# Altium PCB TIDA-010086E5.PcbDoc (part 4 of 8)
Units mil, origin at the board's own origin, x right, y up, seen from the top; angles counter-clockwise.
Board outline 6400 x 6200 mil, 6 copper layers (Top Layer, Power, AGND, Signal, PGND, Bottom Layer), stack 70.536 mil thick; 717 components, 376 nets, 2259 pads, 2183 vias.
Unrouted connection lines stored in the file: 1424.
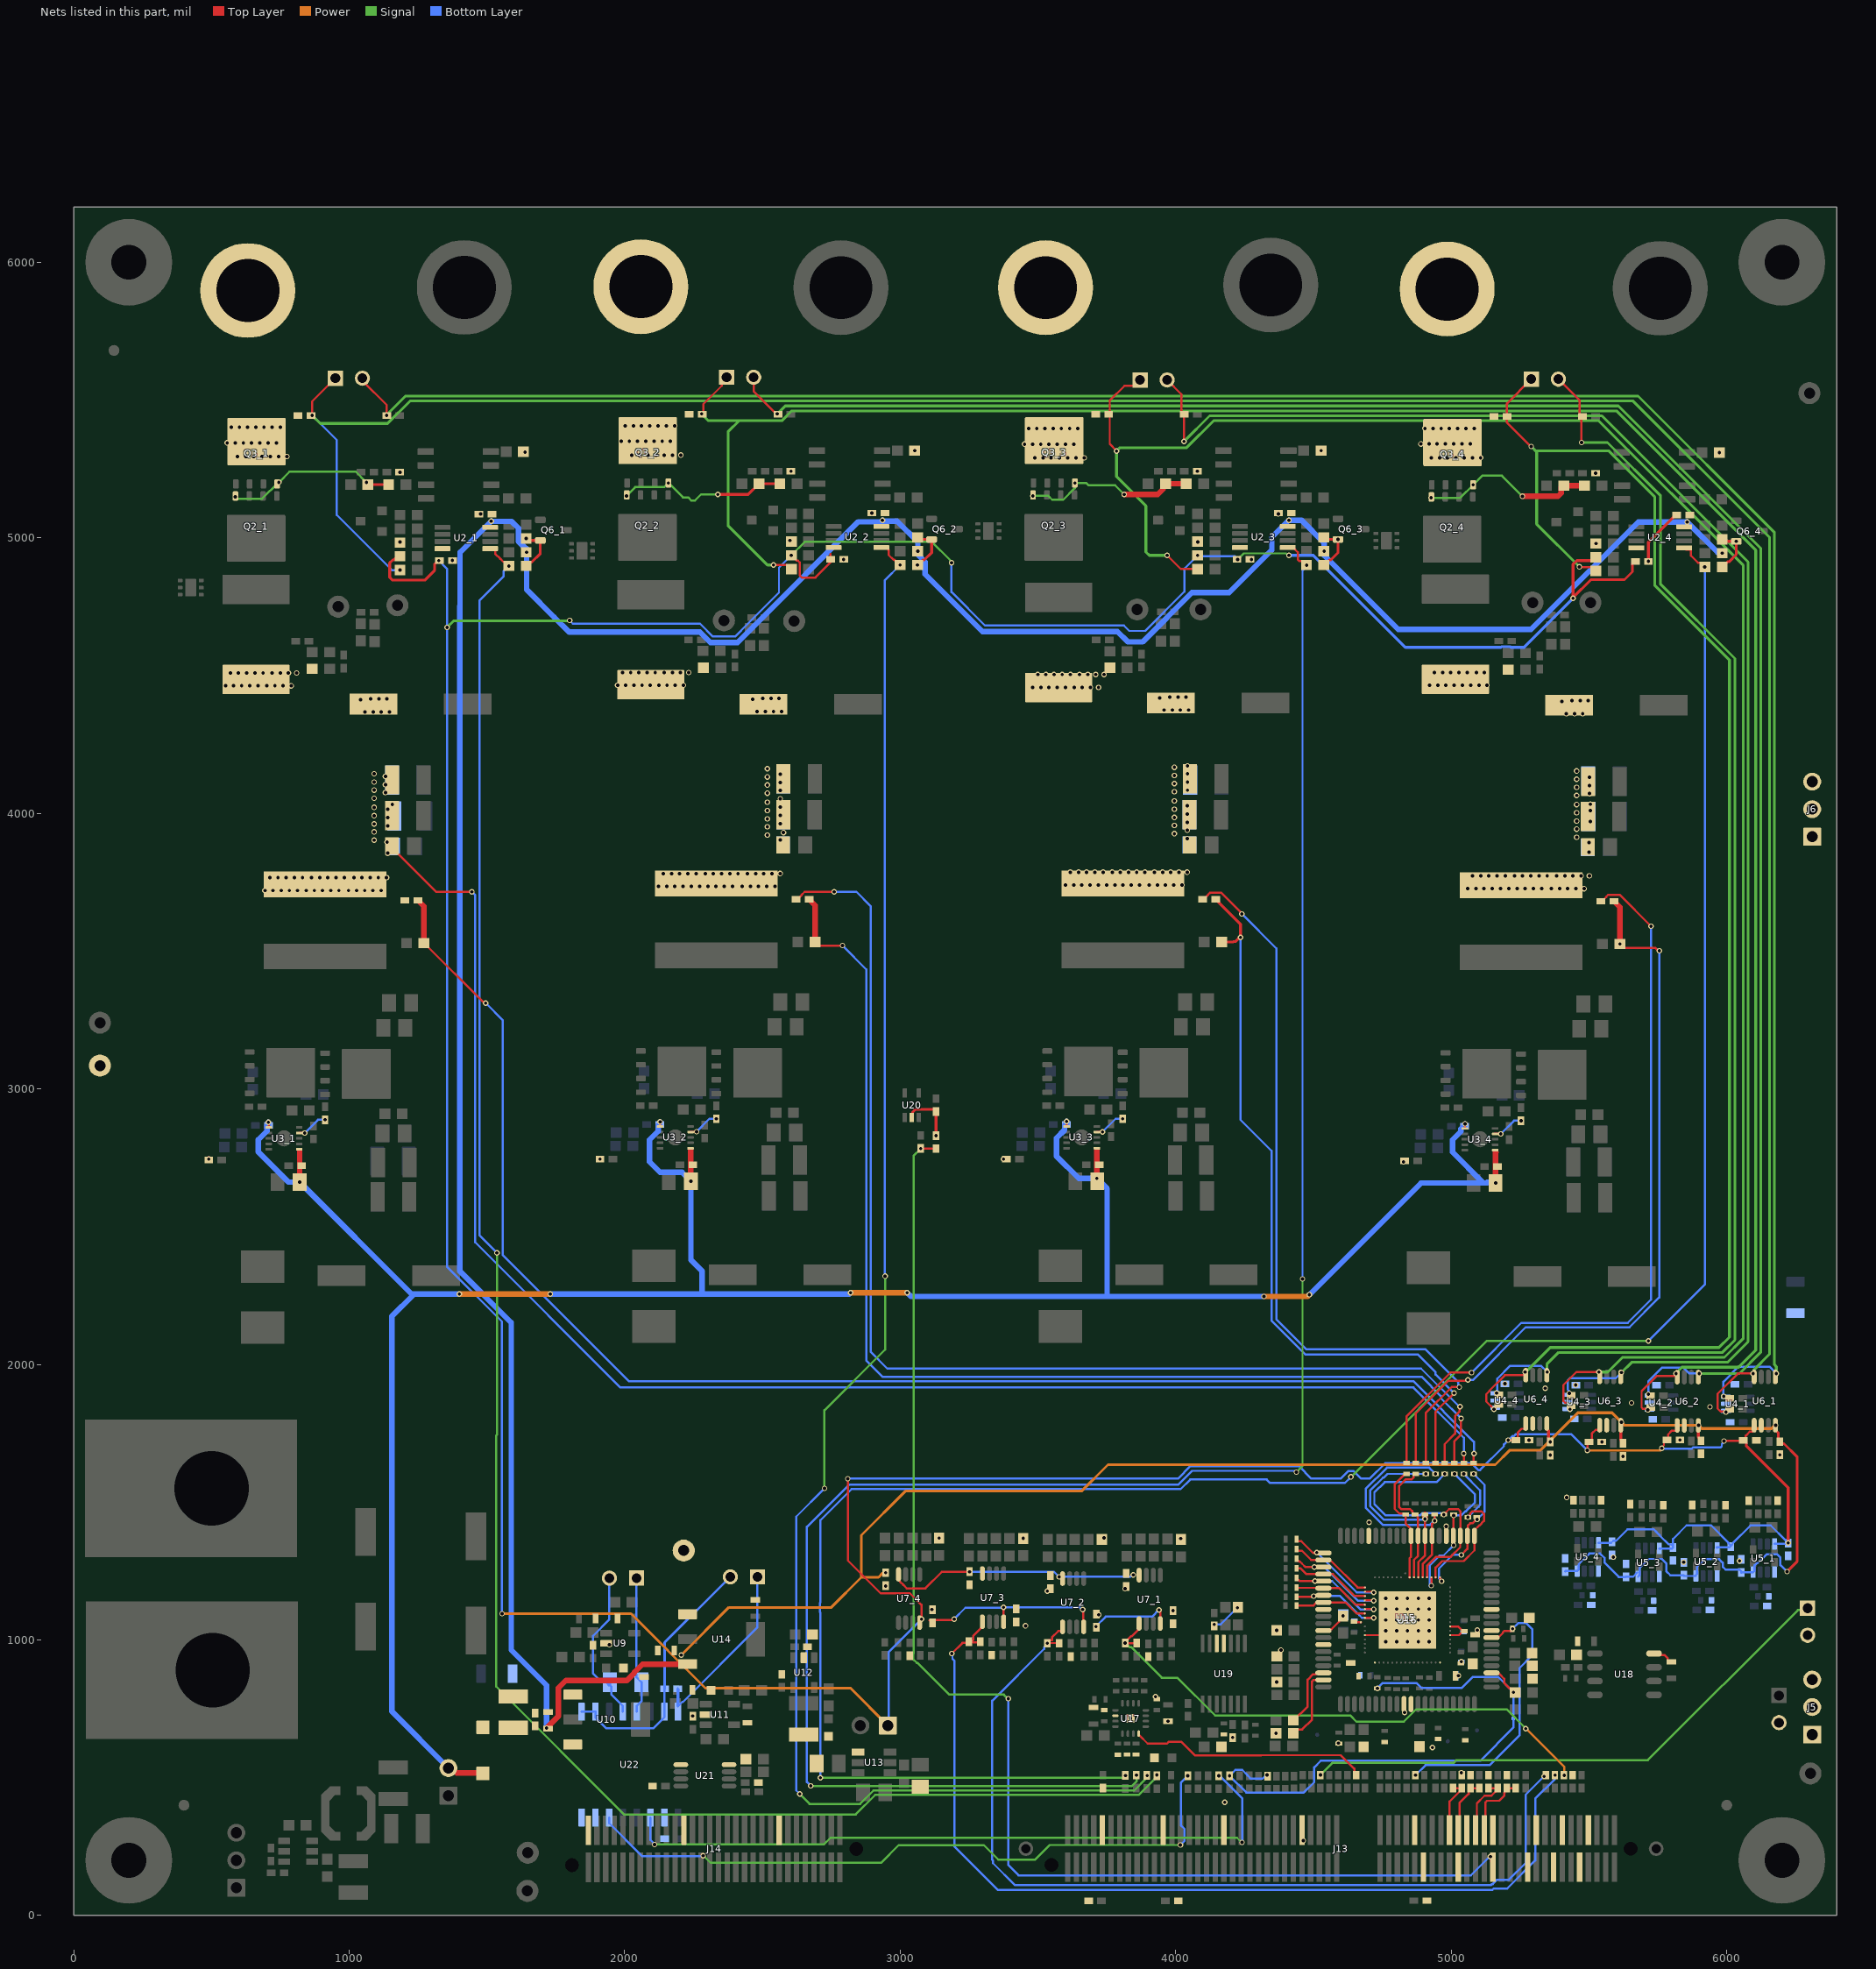
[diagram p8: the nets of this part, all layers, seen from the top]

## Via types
v1: diameter 20, hole 12.5, Top Layer to Bottom Layer, 1408 vias
v2: diameter 20, hole 12, Top Layer to Bottom Layer, tented both sides, 775 vias

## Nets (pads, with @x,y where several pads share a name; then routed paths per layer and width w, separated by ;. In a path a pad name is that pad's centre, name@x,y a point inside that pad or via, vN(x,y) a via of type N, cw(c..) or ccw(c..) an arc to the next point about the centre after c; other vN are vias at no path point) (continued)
10V: C21_1.1 C21_2.1 C21_3.1 C21_4.1 C22_1.2 C22_2.2 C22_3.2 C22_4.2 C26_1.2 C26_2.2 C26_3.2 C26_4.2 J10.2 L3.1 U3_1.1 U3_1.6 U3_2.1 U3_2.6 U3_3.1 U3_3.6 U3_4.1 U3_4.6 | length 9301.3
  Top Layer w7.87: v2(706.18,2878.81) 707.24,2877.75 707.24,2860.39 708.03,2859.61 U3_1.6@708.31,2859.61 ; U3_2.6@2128.43,2863.19 v2(2128.43,2879.92) ; U3_3.6@3603.43,2863.19 v2(3603.43,2881.41) ; U3_4.6@5049.2,2856.35 5049.74,2856.88 5049.74,2872.38 v2(5050.27,2872.91)
  Top Layer w20: v2(820,2661.42) 820,2772.99 ; J10.2@1360,535 1372.17,535 1390.15,517.02 1483.23,517.02 L3.1@1484.97,515.27 ; 2239.39,2775.85 2239.39,2665.73 v2(2240.12,2665) ; v2(3713.66,2675) 3713.66,2776.57 ; v2(5160.9,2658.16) 5160.9,2768.57 5162.07,2769.74
  Power w20: v2(1400,2255) v2(1730,2255) ; v2(2820,2260) v2(3025,2260) ; v2(4320,2246.66) 4478.45,2246.66 4484.46,2252.67 v2(4485,2252.67)
  Bottom Layer w20: v2(706.18,2878.81) 706.18,2868.54 C26_1.2@707.24,2867.48 703.31,2867.48 701.5,2865.67 701.5,2847.01 670,2815.51 670,2771.28 779.86,2661.42 v2(820,2661.42) 1226.42,2255 v2(1400,2255) ; 1230.57,2250.85 1154.52,2174.8 1154.52,740.48 J10.2@1360,535 ; v2(1730,2255) 2280.58,2255 ; v2(2128.43,2879.92) 2127.36,2878.86 C26_2.2@2127.36,2871.06 2123.43,2871.06 2121.61,2869.25 2121.61,2846.2 2090,2814.58 2090,2735.31 2128.26,2697.05 2208.07,2697.05 v2(2240.12,2665) 2240.12,2379.05 2280.58,2338.6 2280.58,2255 ; v2(2820,2260) 2815,2255 2280.58,2255 ; v2(3025,2260) 3038.34,2246.66 3750.8,2246.66 ; v2(3603.43,2881.41) 3603.43,2872.13 C26_3.2@3602.36,2871.06 3598.43,2871.06 3596.61,2869.25 3596.61,2850.77 3567.57,2821.72 3567.57,2755.22 3647.8,2675 v2(3713.66,2675) 3750.8,2637.86 3750.8,2246.66 ; v2(4320,2246.66) 3750.8,2246.66 ; v2(4485,2252.67) 4890.5,2658.16 5116.84,2658.16 ; v2(5050.27,2872.91) 5048.14,2870.79 C26_4.2@5048.14,2864.22 5044.2,2864.22 5034.52,2854.54 5034.52,2845.01 5004.89,2815.38 5004.89,2770.11 5116.84,2658.16 ; 5130.39,2658.16 5116.84,2658.16 ; 5130.39,2661.03 5158.03,2661.03 v2(5160.9,2658.16)
10VA: C23_1.1 C23_2.1 C23_3.1 C23_4.1 C29_1.1 C29_2.1 C29_3.1 C29_4.1 C34_1.1 C34_2.1 C34_3.1 C34_4.1 C39_1.2 C39_2.2 C39_3.2 C39_4.2 C45.2 C48.1 C52.1 C60.1 L3.2 R28_1.2 R28_2.2 R28_3.2 R28_4.2 U2_1.8 U2_2.8 U2_3.8 U2_4.8 U5_1.8 U5_2.8 U5_3.8 U5_4.8 U6_1.8 U6_2.8 U6_3.8 U6_4.8 U7_1.8 U7_2.8 U7_3.8 U7_4.8 U10.3 U14.3 | length 18411.4
  Top Layer w7.87: U7_4.8@2993.8,1237.91 2993.8,1217.53 2998.73,1212.61 2998.73,1211.63 3010.83,1199.53 3023.27,1187.09 3090.97,1187.09 3151.08,1247.2 C39_3.2@3251.51,1247.2 ; v2(3251.33,1247.2) C39_3.2@3257.43,1241.1
  Top Layer w10: U6_4.8@5347.07,1785.42 5347.07,1765.61 5353.14,1759.54 C34_4.1@5353.14,1718.45 ; U6_3.8@5615.12,1779.11 5615.12,1726.05 5623.54,1717.63 C34_3.1@5623.54,1713.7 ; U6_2.8@5896.67,1778.58 5896.67,1735.68 5905.98,1726.37 C34_2.1@5905.98,1722.43 ; v2(6177.37,1779.2) 6177.37,1761.06 6186.67,1751.76 6186.67,1725.38 6199.67,1712.38 6207.78,1712.38 6255,1665.16 6255,1283.95 v2(6218.56,1247.51)
  Top Layer w20: v2(1716.19,680.07) 1759.09,722.97 1759.09,825.61 1786.59,853.1 2007.82,853.1 2035.32,880.6 2035.32,882.96 2064.24,911.89 U14.3@2228.49,911.89
  Power w10: v2(2205,945) 2377.99,1117.99 2749.62,1117.99 2858.67,1227.05 ; v2(2947.19,1244.01) 2945.28,1242.1 2936.07,1242.1 2921.01,1227.05 2858.67,1227.05 ; v2(6177.37,1779.2) 6174.66,1779.2 6162.73,1767.26 5909.13,1767.26 v2(5897.81,1778.58) 5629.17,1778.58 5583.43,1824.32 5459.01,1824.32 5322.58,1687.9 5211.44,1687.9 5159.54,1636 3753.95,1636 3657.95,1540 3019,1540 2858.67,1379.67 2858.67,1227.05
  Bottom Layer w7.87: v2(3251.33,1247.2) 3558.4,1247.2 v2(3576.75,1228.85) 3835.61,1228.85 3842.6,1235.84 v2(3845.85,1235.84) ; C29_4.1@5413.78,1248.4 5415.04,1249.66 U5_4.8@5457.01,1249.66 5461.93,1254.58 5461.93,1274.08 5501.16,1313.31 5540.3,1313.31 5555.78,1297.83 5555.78,1280.68 5608.06,1228.41 C29_3.1@5634.87,1228.41 ; C29_3.1@5634.87,1229.67 5660,1229.67 U5_3.8@5674.95,1244.62 ; U5_3.8@5678.1,1229.67 5683.02,1234.59 5683.02,1260.04 5716.92,1293.95 5764.06,1293.95 5781.25,1276.75 5781.25,1248.24 5794.96,1234.53 C29_2.1@5843.78,1234.53 5843.78,1231.95 U5_2.8@5888.02,1231.95 ; U5_2.8@5886.59,1234.47 5891.68,1239.55 5891.68,1264.43 5920.19,1292.95 5972.4,1292.95 5985.17,1280.17 5985.17,1265.4 5995.32,1255.25 6046,1255.25 6052.82,1248.44 C29_1.1@6052.82,1245.76 ; C29_1.1@6052.82,1244.5 C29_1.1@6052.82,1245.76 ; v2(6218.56,1247.51) 6194.63,1271.44 6194.63,1298.56 6181.85,1311.33 6145.44,1311.33 6132.66,1298.56 6131.9,1298.56 6111.59,1278.24 6109.03,1278.24 6100.97,1270.18 6100.97,1250.68 U5_1.8@6096.04,1245.76 C29_1.1@6052.82,1245.76
  Bottom Layer w20: v2(1716.19,680.07) 1716.19,835.59 1587.87,963.91 1587.87,2152.13 1401.38,2338.62 1401.38,4752.22 1402.35,4753.19 1402.35,4947.05 v2(1515.34,5060.04) 1515.72,5059.66 1589.5,5059.66 1614.47,5034.69 1614.47,4986.21 1630.8,4969.88 1633.24,4969.88 1643.65,4959.47 v2(1643.65,4947.76) 1643.65,4812.35 1743.8,4712.2 1798.13,4657.87 2272.73,4657.87 2310.61,4620 2409.39,4620 2468.64,4679.25 2847.38,5057.99 2929.82,5057.99 v2(2935.46,5063.62) 2938.33,5060.75 2988.29,5060.75 3063.77,4985.27 v2(3063.77,4951.34) 3063.77,4939.45 3090.34,4912.88 3090.34,4867.97 3298.31,4660 3788.15,4660 3826.03,4622.13 3879.88,4622.13 4058.42,4800.67 4193.48,4800.67 4348.5,4955.69 4348.5,5001.67 v2(4410.46,5063.62) 4410.84,5063.24 4456.76,5063.24 4538.77,4981.23 v2(4538.77,4951.34) 4538.77,4935.83 4807.47,4667.13 5288.97,4667.13 5678.63,5056.78 v2(5856.24,5056.78) 5966.22,4946.8 5980.95,4946.8 v2(5983.24,4944.5)
  other v2: 5359.01,1718.28 5617.62,1790.13
-5VA: C25_1.1 C25_2.1 C25_3.1 C25_4.1 C33_1.1 C33_2.1 C33_3.1 C33_4.1 C36_1.2 C36_2.2 C36_3.2 C36_4.2 C38_1.2 C38_2.2 C38_3.2 C38_4.2 J12.1 R20_1.2 R20_2.2 R20_3.2 R20_4.2 U2_1.4 U2_2.4 U2_3.4 U2_4.4 U5_1.4 U5_2.4 U5_3.4 U5_4.4 U6_1.5 U6_2.5 U6_3.5 U6_4.5 U7_1.4 U7_2.4 U7_3.4 U7_4.4 | length 18960.3
  Top Layer w7.87: v2(2604.47,4936.34) 2605.46,4936.34 2624.95,4916.85 2629.05,4916.85 2635.97,4909.93 2635.97,4862.75 2642.89,4855.83 2692.04,4855.83 2747.35,4911.13 C25_2.1@2747.35,4921.34 2747.35,4940.61 ; v2(2809.65,1585) 2809.65,1288.28 2928.71,1169.21 3035.15,1169.21 3077.18,1127.19 v2(3077.18,1075) U7_4.4@3071.73,1080.45 ; 3105.21,1070 3117.19,1070 3119.71,1072.52 3190.27,1072.52 3192.75,1075 v2(3196,1075) ; U7_3.4@3374.9,1065.9 v2(3374.9,1117.99) ; v2(3662.16,1110.48) 3664.37,1108.27 3664.37,1048.84 U7_2.4@3665.85,1047.37 ; v2(3710,1048.19) 3710.7,1048.19 C38_2.2@3712.46,1046.42 ; v2(3938.99,1108.94) 3938.99,1105.69 3943.68,1100.99 U7_1.4@3943.68,1059.69 ; v2(5206.38,1724.83) C36_4.2@5234.63,1724.83 5240.89,1731.1 5240.89,1751.64 5255.47,1766.22 5266.73,1766.22 5270.3,1769.79 U6_4.5@5270.3,1785.42 ; v2(5493.91,1687.9) 5493.91,1712.88 C36_3.2@5499.48,1718.45 ; C36_3.2@5509.97,1721.6 5509.97,1748.41 5524.55,1762.99 5535.81,1762.99 5539.37,1766.55 U6_3.5@5539.37,1782.18 ; v2(5763.99,1695.56) 5763.99,1698.81 5771.93,1706.74 5771.93,1718.76 5778.74,1725.57 C36_2.2@5782.68,1725.57 5786.91,1729.81 5786.91,1745.6 5800.7,1759.39 5816.33,1759.39 5819.89,1762.95 U6_2.5@5819.89,1778.58 ; v2(5989.74,1721.6) 5990.73,1722.59 6058.7,1722.59 C36_1.2@6059.7,1723.58 ; C36_1.2@6068.82,1724.18 6068.82,1741.23 6083.4,1755.81 6094.66,1755.81 6098.23,1759.37 U6_1.5@6098.23,1775
  Top Layer w10: R20_1.2@1184.35,4932.76 1175.65,4924.06 1166.05,4924.06 1161.33,4919.33 1157.27,4919.33 1146.8,4908.86 1146.8,4856.65 1157.27,4846.18 1274.44,4846.18 1309.35,4881.1 1309.35,4903.82 C25_1.1@1323.29,4917.76 ; v2(5442.11,4780.4) v2@5442.11,4783.1 ; 5442.11,4857.43 v2@5442.11,4783.1 ; 5442.11,4858.43 5442.11,4903.98 5455.51,4917.37 5513.13,4917.37 R20_4.2@5525.25,4929.5 ; C25_4.1@5667.8,4914.82 5664.51,4914.82 5657.38,4907.69 5657.38,4876.59 5628.72,4847.93 5506.93,4847.93 v2@5442.11,4783.1 ; C36_1.2@6059.7,1723.58 6063.63,1723.58 6065.93,1721.28 6070.44,1716.77 6070.44,1704.61 6222.82,1552.24 v2(6222.82,1351.75)
  Signal w7.87: v2(2604.47,4936.34) 2653.13,4985 3115,4985 3180.66,4919.34 3180.66,4918.25 3186.02,4912.89 v2(3186.02,4909.6) ; v2(4225,4921.61) 4246.81,4943.42 4400.1,4943.42 4407.18,4936.34 v2(4410.46,4936.34)
  Signal w10: v2(1355,4675) 1378.19,4698.19 1798.19,4698.19 v2(1800,4700)
  Power w7.87: v2(5493.91,1687.9) 5494.27,1688.26 5759.65,1688.26 5763.99,1692.61 v2(5763.99,1695.56)
  Power w10: v2(1555,1095) 2022.65,1095 2292.65,825 2819.56,825 J12.1@2955.18,689.38
  Bottom Layer w7.87: v2(1325,4917.31) 1355,4887.31 1355,2354.15 1554.18,2154.97 v2@1554.18,1095 ; v2(1800,4700) 1811.72,4688.28 2273.17,4688.28 2319.64,4641.81 2400.36,4641.81 2446.83,4688.28 2559.73,4801.18 2559.73,4891.6 v2(2604.47,4936.34) ; v2(2809.65,1585) 4007.96,1585 4053.43,1630.47 4446.89,1630.47 4492.36,1585 4598.41,1585 4626.92,1613.52 4644.99,1613.52 4673.51,1585 4703.74,1585 4759.82,1641.08 5073.18,1641.08 5097.78,1616.48 5104.3,1616.48 5191.31,1703.49 5191.31,1709.06 5206.38,1724.13 v2(5206.38,1724.83) 5207.08,1724.83 5222.15,1739.91 5227.72,1739.91 5234.46,1746.64 5435.17,1746.64 v2(5493.91,1687.9) ; J12.1@2955.18,689.38 2958.63,692.83 2958.63,956.46 v2(3077.18,1075) ; v2(3186.02,4909.6) 3186.02,4803.13 3307.34,4681.81 3811.29,4681.81 3831.14,4661.96 3888.86,4661.96 4031.4,4804.5 4031.4,4888.27 v2(4079.47,4936.34) ; v2(3196,1075) 3196,1076 3236.5,1116.5 3373.4,1116.5 v2(3374.9,1117.99) 3651.4,1117.99 3658.92,1110.48 v2(3662.16,1110.48) ; v2(3710,1048.19) 3745.98,1084.16 3914.21,1084.16 v2(3938.99,1108.94) ; v2@4079.47,4933.38 4080.11,4934.02 4089.51,4934.02 4090.15,4933.38 4213.22,4933.38 v2(4225,4921.61) ; U5_4.4@5533.78,1352.02 5580.16,1352.02 5588.16,1360.03 5598.5,1360.03 5639.78,1401.3 5735.23,1401.3 5743.59,1392.95 5756.37,1380.17 5756.37,1379.02 5788.99,1346.4 5798.06,1346.4 C33_3.1@5804.87,1339.59 ; U5_3.4@5754.87,1332.03 5801.25,1332.03 C33_3.1@5804.87,1335.65 C33_3.1@5804.87,1339.59 ; v2(5763.99,1695.56) 5765.99,1693.57 5872.53,1693.57 5877.11,1698.15 5976.77,1698.15 5981.85,1703.22 5981.85,1710.43 5989.74,1718.31 v2(5989.74,1721.6) ; U5_2.4@5964.79,1334.32 5964.79,1335.4 5963.36,1336.83 6009.74,1336.83 C33_2.1@6012.82,1339.91 ; U5_1.4@6174.02,1349.33 U5_1.4@6172.82,1348.12 6219.19,1348.12 v2(6222.82,1351.75) 6222.82,1355.68 6216,1362.49 6212.07,1362.49 6159.05,1415.51 6086.52,1415.51 6021.6,1350.59 6021.6,1348.69 6016.7,1343.78 6012.88,1343.78 6006.91,1349.75 6006.91,1351.66 5943.06,1415.51 5853.99,1415.51 5804.87,1366.4 C33_3.1@5804.87,1339.59
  Bottom Layer w10: v2(4410.46,4936.34) 4499.26,4936.34 4833.47,4602.13 5179.47,4602.13 5181.65,4604.3 5214.62,4604.3 5216.65,4602.28 5263.99,4602.28 v2(5442.11,4780.4)
AGND: C23_1.2 C23_2.2 C23_3.2 C23_4.2 C25_1.2 C25_2.2 C25_3.2 C25_4.2 C27_1.1 C27_2.1 C27_3.1 C27_4.1 C28_1.1 C28_2.1 C28_3.1 C28_4.1 C29_1.2 C29_2.2 C29_3.2 C29_4.2 C30_1.1 C30_2.1 C30_3.1 C30_4.1 C32_1.1 C32_2.1 C32_3.1 C32_4.1 C33_1.2 C33_2.2 C33_3.2 C33_4.2 C34_1.2 C34_2.2 C34_3.2 C34_4.2 C36_1.1 C36_2.1 C36_3.1 C36_4.1 C38_1.1 C38_2.1 C38_3.1 C38_4.1 C39_1.1 C39_2.1 C39_3.1 C39_4.1 C45.1 C46.2 C47.2 C48.2 C49.2 C50.2 C51.2 C52.2 C53.1 C54.1 C55.2 C56.1 C58.2 C59.2 C60.2 C61.2 C62.2 C63.2 C64.1 C65.1 C66.1 C67.2 C68.1 C69.1 C70.1 C71.1 C72.1 C73.1 C74.1 C75.1 C76.1 C77.1 C78.2 C79.2 C80.2 C81.2 C82.1 C83.2 C84.2 C85.1 C86.2 C87.2 C88.2 C89.2 C90.2 C91.2 C92.1 C93.2 C94.2 C95.1 C96.1 C97.1 C98.1 C99.1 C100.1 C101.1 C102.2 C103.1 C104.1 C106.1 D1.1 D2.1 D3.1 D4.1 J3.2 J4.2 J5.1 J5.2 J5.3 J6.1 J6.2 J6.3 J13.7 J13.10 J13.13 J13.16 J13.19 J13.22 J13.29 J13.35 J13.38 J13.46 J13.47 J13.65 J13.83 J13.97 J13.111 J14.135 J14.157 J14.179 Q6_1.2 Q6_2.2 Q6_3.2 Q6_4.2 R22_1.1 R22_2.1 R22_3.1 R22_4.1 R26_1.1 R26_2.1 R26_3.1 R26_4.1 R29_1.2 R29_2.2 R29_3.2 R29_4.2 R30_1.1 R30_2.1 R30_3.1 R30_4.1 R31_1.2 R31_2.2 R31_3.2 R31_4.2 R35_1.1 R35_2.1 R35_3.1 R35_4.1 R38_1.1 R38_2.1 R38_3.1 R38_4.1 R40_1.1 R40_2.1 R40_3.1 R40_4.1 R45_1.1 R45_2.1 R45_3.1 R45_4.1 R48_1.1 R48_2.1 R48_3.1 R48_4.1 R55.1 R56.2 R71.2 R75.2 R77.2 R79.2 R82.1 R84.1 R85.1 R86.1 R91.2 R93.2 R98.2 R105.2 R106.2 R107.2 R113.1 R116.2 R156.2 TP5.1 TP6.1 U4_1.2 U4_2.2 U4_3.2 U4_4.2 U5_1.5 U5_2.5 U5_3.5 U5_4.5 U6_1.6 U6_2.6 U6_3.6 U6_4.6 U9.2 U10.1 U11.2 U12.2 U13.1 U14.1 U15.25 U15.28 U15.33 U15.48 U15.53 U15.55 U15.65 U16.5 U16.16 U16.29 U16.32 U16.34 U16.50 U16.51 U16.69 U16.72 U17.6 U17.17 U18.4 U19.11 U19.12 U20.2 U21.4 U21.5 U22.2 U22.7 U22.8 | length 1734.8
  Top Layer w7.87: R22_1.1@1184.35,4982.76 v2(1184.35,4985) ; R29_1.2@1632.35,5312.76 1632.35,5311.96 R29_1.2@1634.31,5310 ; U16.32@4535.93,1033.97 4559.26,1033.97 4564.18,1038.89 4565.16,1038.89 4592.09,1065.82 C79.2@4592.09,1072.13 ; C72.1@4646.25,1066.5 4648.27,1064.48 U15.25@4671.75,1064.48 ; U15.28@4686.52,1017.23 4785.93,1017.23 v2(4801.67,1032.98) v2(4841.04,1072.35) ; U16.5@4981.79,1377.47 v2(4981.79,1412.02) ; U15.53@4995.98,1017.23 5028.33,1017.23 C71.1@5042.44,1031.35 ; U15.55@4995.98,1048.73 5025.06,1048.73 C71.1@5042.44,1031.35 ; C71.1@5046.94,1031.35 C71.1@5042.44,1031.35 ; U18.4@5735.92,950.5 5756.34,950.5 5762.63,944.21 5774.93,944.21 5786.14,933 5786.14,925.5 5791.14,920.5 C86.2@5798.64,920.5
  Top Layer w10: R31_1.2@1183.14,5237.76 1184.04,5237.76 v2(1184.35,5237.44) ; R26_1.1@1642.35,4897.76 1656.05,4911.46 1662.64,4911.46 1693.61,4942.42 Q6_1.2@1693.61,4990.35 1649.75,4990.35 v2(1642.35,4997.76) ; v2(2599.29,4990.35) 2600.46,4990.35 R22_2.1@2604.47,4986.34 ; U20.2@3041.86,2896.18 3044.73,2899.05 3044.73,2915.12 3055.39,2925.78 3125.24,2925.78 3130,2921.02 v2(3130,2830.31) ; v2(3062.46,4901.34) 3063.45,4901.34 3081.87,4919.76 3087.48,4919.76 3113.72,4946.01 Q6_2.2@3113.72,4993.94 3069.87,4993.94 R30_2.1@3062.46,5001.34 ; R26_3.1@4537.46,4901.34 4538.45,4901.34 4556.87,4919.76 4562.48,4919.76 4588.72,4946.01 v2(4588.72,4993.94) 4544.87,4993.94 R30_3.1@4537.46,5001.34 ; v2(5715.37,4914.5) 5715.37,4984.19 5813.99,5082.81 C23_4.2@5817.93,5082.81 ; R26_4.1@5983.24,4894.5 5984.23,4894.5 6002.65,4912.93 6008.26,4912.93 6034.5,4939.17 v2(6034.5,4987.1) 5990.65,4987.1 R30_4.1@5983.24,4994.5
  Top Layer w20: C27_1.1@490,2741.42 v2(490,2745)
  Bottom Layer w7.87: v2(4139.24,1056.42) 4163.36,1056.42 v2(4223.86,1116.92)
  other v2: 4463.31,271.2 4177.95,410.75 5036.62,518.06 4931.86,609.22 4590,625 4206.6,645.78 4363.64,661.05 3971.43,704.48 3836.01,714.88 2246.65,723.55 4830.7,736.84 3926.66,794.13 4366.42,847.14 5026.39,870 5036.62,920.88 4381.76,962.78 1944.29,982.05 4762.3,993.61 4801.67,993.61 4841.04,993.61 4880.41,993.61 4919.78,993.61 4762.3,1032.98 4841.04,1032.98 4880.41,1032.98 4919.78,1032.98 4366.16,1034.55 5094.41,1035.73 3454.65,1051.04 4762.3,1072.35 4801.67,1072.35 4880.41,1072.35 4919.78,1072.35 4606.85,1086.9 3720.75,1091.33 3990.3,1105.99 3115,1110.48 4762.3,1111.72 4801.67,1111.72 4841.04,1111.72 4880.41,1111.72 4919.78,1111.72 4762.3,1151.09 4801.67,1151.09 4841.04,1151.09 4880.41,1151.09 4919.78,1151.09 3533.43,1177.04 3816.32,1186.05 2947.19,1195 5843.78,1281.77 6046.16,1286.65 5588.56,1300.55 3446.51,1368.4 4017.95,1367.6 3141.03,1369.64 3740.02,1370.1 4702.06,1426.43 5419.11,1516.99 5623.54,1666.45 5359.01,1671.04 6192.87,1671.94 5546.73,1718.45 5281.87,1724.83 5829.92,1725.57 5939.2,1845.57 5653.98,1860.27 5341.16,1913.64 5451.67,1925.07 5194.52,1929.83 4826.6,2734.58 1910.12,2745 3375,2744.76 1374.47,4917.76 2794.59,4921.34 4275,4921.61 5525.25,4979.5 4080,4985 1476.81,5086.26 4372.15,5086.34 2897.15,5089.65 5524.04,5234.5 2603.26,5241.34 4078.26,5241.34 1638.44,5310.49 5973.24,5309.5 3052.46,5316.34 4527.46,5316.34
AINM5: R165.2 R166.2 U15.2 U16.1 | length 627.6
  Top Layer w7.87: U15.2@4943.41,1226.88 4943.41,1262.2 4967.18,1285.98 5045.26,1285.98 5084.15,1324.88 5084.15,1398.14 5101.1,1415.09 5102.03,1415.09 5118.81,1431.87 5118.81,1457.39 5109.51,1466.69 5077.24,1466.69 5068.06,1457.52 5068.06,1448.56 5064.5,1445 v2(5060,1445) ; v2(5045.06,1602.23) 5045.3,1602.46 R165.2@5045.53,1602.46
  Bottom Layer w7.87: v2(5045.06,1602.23) 5105,1542.29 5105,1490 v2(5060,1445)
AINM6: R169.2 R170.2 U15.4 U16.3 | length 996.1
  Top Layer w7.87: U15.4@4911.91,1227.29 4911.91,1268.89 4944.76,1301.73 4998.08,1301.73 5032.48,1336.13 5032.48,1376.98 U16.3@5032.97,1377.47 5032.97,1466.94 5025.6,1474.31 4991.81,1474.31 4980.7,1463.2 4980.7,1458.56 4977.13,1455 v2(4972.63,1455) ; R169.2@4975.53,1602.46 4975.79,1602.46 v2(4976.03,1602.23)
  Bottom Layer w7.87: v2(4972.63,1455) 4969.35,1455 4963.48,1460.88 4895.43,1460.88 4886.07,1451.51 4762.65,1451.51 4720.81,1493.35 4720.81,1535.26 4758.36,1572.81 4946.62,1572.81 v2(4976.03,1602.23)
AINM7: R173.2 R174.2 U15.6 U16.8 | length 743.5
  Top Layer w7.87: U15.6@4880.41,1226.88 4880.41,1281.93 4905.02,1306.54 U16.8@4905.02,1377.47 4904.74,1377.75 4904.74,1438.79 v2(4904.47,1439.07)
  Top Layer w20: v2(4904.47,1439.07) R174.2@4904.47,1455
  Bottom Layer w7.87: v2(4904.47,1439.07) 4902.15,1436.75 4894.78,1436.75 4893.79,1435.76 4756.13,1435.76 4705.06,1486.83 4705.06,1541.78 4751.84,1588.56 4754.04,1588.56 4767.94,1602.46 v2(4907.97,1602.46)
AINM8: R177.2 R178.2 U15.8 U16.10 | length 433.2
  Top Layer w7.87: R177.2@4837.02,1602.46 4832.52,1602.46 4794.56,1564.51 4794.56,1476.08 4812.08,1458.56 4830.56,1458.56 R178.2@4834.12,1455 4834.12,1422.85 4849.59,1407.37 4849.59,1405.05 4853.84,1400.8 4853.84,1301.87 4848.92,1296.95 U15.8@4848.92,1226.88
AINM13: R88.2 U15.18 U16.21 | length 421.1
  Top Layer w7.87: R88.2@4438.38,1365.45 4438.38,1362.01 4441.95,1358.45 4455.53,1358.45 4498.52,1315.46 U16.21@4513.44,1315.46 ; v2(4511.93,1316.97) U16.21@4513.44,1315.46 ; U16.21@4535.93,1315.46 U16.21@4513.44,1315.46 ; U15.18@4686.52,1174.71 4716.2,1174.71 v2(4718.64,1172.28)
  Bottom Layer w7.87: v2(4511.93,1316.97) 4656.63,1172.28 4716.3,1172.28 v2@4717.23,1173.21
AINM14: R94.2 U15.20 U16.23 | length 412
  Top Layer w7.87: R94.2@4438.38,1295.45 4438.38,1290.95 4441.95,1287.38 4446.45,1287.38 4449.57,1284.26 4450.78,1284.26 4457.7,1277.34 4457.7,1277.25 4470.66,1264.28 U16.23@4535.93,1264.28 ; U15.20@4686.1,1143.22 4716.81,1143.22 v2(4718.21,1141.82)
  Bottom Layer w7.87: v2(4502.73,1264.28) 4538.99,1264.28 4661.46,1141.82 v2(4718.21,1141.82)
AINM15: R96.2 U15.22 U16.25 | length 393.2
  Top Layer w7.87: R96.2@4438.38,1225.45 4438.38,1220.95 4441.95,1217.38 4446.45,1217.38 4450.08,1213.75 v2(4505.12,1213.75) 4505.77,1213.1 U16.25@4535.93,1213.1 ; U15.22@4686.52,1111.72 4717.23,1111.72 v2(4718.21,1110.74)
  Bottom Layer w7.87: v2(4505.12,1213.75) 4567.25,1213.75 4670.27,1110.74 v2(4718.21,1110.74)
AINM16: R99.2 U15.24 U16.27 | length 380.9
  Top Layer w7.87: R99.2@4438.38,1156.78 v2@4500.37,1156.78 ; v2(4500.37,1158.97) 4501.84,1160.44 4534.45,1160.44 U16.27@4535.93,1161.92 ; U15.24@4686.52,1080.23 v2(4718.21,1080.23)
  Bottom Layer w7.87: v2(4500.37,1158.97) 4596.76,1158.97 4665.85,1089.88 4666.01,1089.88 4675.66,1080.23 v2(4718.21,1080.23)
AINP5: R43.2 R72.2 U15.1 U16.2 | length 528.7
  Top Layer w7.87: U15.1@4959.15,1226.88 4959.15,1222.44 4965.22,1216.38 v2(4965.22,1213.1) ; v2(5036.62,1308.42) 5058.56,1330.37 U16.2@5058.56,1377.47 5060.04,1378.95 5060.04,1414.54 5068.69,1423.19 5076.71,1423.19 5090.84,1437.32 v2(5093.42,1437.32) 5093.42,1445.33 R72.2@5092.75,1446
  Bottom Layer w7.87: v2(4965.22,1213.1) 4955.22,1223.1 4955.22,1258.87 5004.77,1308.42 v2(5036.62,1308.42) ; v2(5080.95,1602.46) 5120.75,1562.66 5120.75,1464.65 v2(5093.42,1437.32)
AINP6: R167.2 R168.2 U15.3 U16.4 | length 562.1
  Top Layer w7.87: v2(4927.66,1197.02) U15.3@4927.66,1226.88 ; R168.2@5008.04,1451.5 5008.04,1378.13 U16.4@5007.38,1377.47 5008.04,1376.81 5008.04,1343.87 v2(5008.7,1343.21) ; v2(5011.6,1602.23) R167.2@5011.6,1602.46
  Bottom Layer w7.87: v2@4922.63,1195.22 4922.63,1270.84 4957.66,1305.86 4971.36,1305.86 v2(5008.7,1343.21) ; v2(5008.7,1451.5) 5035.65,1451.5 5050.97,1466.81 5053.74,1466.81 5086.36,1499.43 5086.36,1527.47 v2(5011.6,1602.23)
AINP7: R171.2 R172.2 U15.5 U16.7 | length 891.2
  Top Layer w7.87: U15.5@4896.16,1227.29 4896.16,1275.41 4930.61,1309.86 4930.61,1421.37 4939.47,1430.23 R172.2@4939.47,1455 ; R171.2@4942.37,1602.46 v2(4942.62,1602.46)
  Bottom Layer w7.87: v2(4939.47,1432.04) 4936.22,1432.04 4921.18,1417 4752.62,1417 4689.31,1480.31 4689.31,1548.3 4766.34,1625.33 4919.75,1625.33 v2(4942.62,1602.46)
AINP8: R175.2 R176.2 U15.7 U16.9 | length 474.6
  Top Layer w7.87: U15.7@4864.67,1227.29 4864.67,1290.42 4879.43,1305.19 4879.43,1444.23 4876.72,1446.94 4876.72,1451.44 4873.16,1455 4864.16,1455 4860.59,1458.56 4860.59,1462.17 4857.93,1464.83 4857.93,1467.39 4850.32,1475 4817.92,1475 4810.31,1482.61 4810.31,1507.39 4810.69,1507.77 4810.69,1558.36 4835.48,1583.15 4856.89,1583.15 4863.65,1589.91 4863.65,1598.9 4867.21,1602.46 R175.2@4871.56,1602.46
AINP13: R87.2 U15.17 U16.22 | length 303.5
  Top Layer w7.87: R87.2@4438.89,1325.44 4440.88,1323.45 4457.88,1323.45 4491.46,1289.87 4558.68,1289.87 4562.54,1286.01 4564.28,1286.01 4659.83,1190.46 U15.17@4686.52,1190.46
AINP14: R89.2 U15.19 U16.24 | length 290.2
  Top Layer w7.87: R89.2@4438.38,1260.45 4439.31,1259.52 4453.08,1259.52 4473.91,1238.69 U16.24@4535.93,1238.69 4536.12,1238.5 4569.88,1238.5 4649.41,1158.97 U15.19@4686.52,1158.97
AINP15: R95.2 U15.21 U16.26 | length 273.8
  Top Layer w7.87: R95.2@4438.38,1190.45 4439.85,1188.98 4534.46,1188.98 U16.26@4535.93,1187.51 4593.11,1187.51 4653.15,1127.47 U15.21@4686.1,1127.47
AINP16: R97.2 U15.23 U16.28 | length 269.3
  Top Layer w7.87: R97.2@4438.35,1124.62 4499.9,1124.62 4509.73,1134.45 4534.04,1134.45 U16.28@4535.93,1136.33 4615.33,1136.33 4655.69,1095.97 U15.23@4686.1,1095.97
BATP_1: J7_1.1 Q3_1.5 Q3_1.6 Q3_1.7 Q3_1.8 Q3_1.9@663.46,5348.94 R6_1.1
  other v1: 594.74,5294.88 624.43,5294.88 653.56,5294.88 683.56,5294.88 713.56,5294.88 743.56,5294.88 773.56,5294.88 556.97,5344.81 586.65,5344.81 615.79,5344.81 645.79,5344.81 675.79,5344.81 705.79,5344.81 735.79,5344.81 571.73,5401.44 601.42,5401.44 630.55,5401.44 660.55,5401.44 690.55,5401.44 720.55,5401.44 750.55,5401.44
BATP_2: J7_2.1 Q3_2.5 Q3_2.6 Q3_2.7 Q3_2.8 Q3_2.9@2083.58,5352.52 R6_2.1
  other v1: 2024.82,5300 2054.5,5300 2083.64,5300 2113.64,5300 2143.64,5300 2173.64,5300 2203.64,5300 1987.04,5349.93 2016.73,5349.93 2045.86,5349.93 2075.86,5349.93 2105.86,5349.93 2135.86,5349.93 2165.86,5349.93 2001.81,5406.55 2031.49,5406.55 2060.63,5406.55 2090.63,5406.55 2120.63,5406.55 2150.63,5406.55 2180.63,5406.55
BATP_3: J7_3.1 Q3_3.5 Q3_3.6 Q3_3.7 Q3_3.8 Q3_3.9@3558.58,5352.52 R6_3.1
  other v1: 3488.92,5290.07 3518.61,5290.07 3547.74,5290.07 3577.74,5290.07 3607.74,5290.07 3637.74,5290.07 3667.74,5290.07 3451.15,5340 3480.84,5340 3509.97,5340 3539.97,5340 3569.97,5340 3599.97,5340 3629.97,5340 3465.91,5396.62 3495.6,5396.62 3524.73,5396.62 3554.73,5396.62 3584.73,5396.62 3614.73,5396.62 3644.73,5396.62
BATP_4: J7_4.1 Q3_4.5 Q3_4.6 Q3_4.7 Q3_4.8 Q3_4.9@5004.36,5345.68 R6_4.1
  other v1: 4927.6,5290.6 4957.29,5290.6 4986.42,5290.6 5016.42,5290.6 5046.42,5290.6 5076.42,5290.6 5106.42,5290.6 4889.83,5340.53 4919.51,5340.53 4948.65,5340.53 4978.65,5340.53 5008.65,5340.53 5038.65,5340.53 5068.65,5340.53 4904.59,5397.15 4934.28,5397.15 4963.41,5397.15 4993.41,5397.15 5023.41,5397.15 5053.41,5397.15 5083.41,5397.15
BATSN1: J8_1.2 R9_1.2 R39_1.2 U4_1.3 U6_1.1 | length 8797.2
  Top Layer w7.87: J8_1.2@1047.94,5579.08 1047.94,5570.39 1135.9,5482.43 v2(1135.9,5444.08) ; v2(6179.79,1966.76) U6_1.1@6181.07,1966.76
  Top Layer w10: v2(5988.86,1883.89) 5990.77,1881.98 6005.14,1881.98 R39_1.2@6010.33,1876.79
  Signal w10: v2(1135.9,5444.08) 1135.9,5446.05 1204.21,5514.37 5677.94,5514.37 6172.87,5019.43 6172.87,1998.65 6179.79,1991.73 v2(6179.79,1966.76)
  Bottom Layer w7.87: U4_1.3@5987.63,1889.49 5987.63,1936.7 6042.35,1991.43 6155.13,1991.43 v2(6179.79,1966.76)
BATSN2: J8_2.2 R9_2.2 R39_2.2 U4_2.3 U6_2.1 | length 7413.3
  Top Layer w7.87: J8_2.2@2468.06,5582.67 2468.06,5531.68 R9_2.2@2552.08,5447.67 ; v2(2553.61,5450) 2555.94,5447.67 R9_2.2@2556.01,5447.67
  Signal w7.87: J8_2.2@2468.06,5582.67 J8_2.2@2477.93,5582.67
  Signal w10: v2(2553.61,5450) 2582.23,5478.62 5606.75,5478.62 6122.87,4962.5 6122.87,2043.72 6045.92,1966.76 v2(5899.93,1966.76)
  Bottom Layer w7.87: v2(5715.45,1891.49) 5715.79,1891.49 5715.79,1939.33 5765.03,1988.57 5842.07,1988.57 5863.88,1966.76 v2(5899.93,1966.76)
BATSN3: J8_3.2 R9_3.2 R39_3.2 U4_3.3 U6_3.1 | length 6152.4
  Top Layer w7.87: J8_3.2@3968.85,5572.67 4020,5521.51 4020,5460.33 4020.27,5460.07 4020.27,5454.48 R9_3.2@4027.08,5447.67 ; v2(4030,5350) 4030,5444.74 R9_3.2@4027.08,5447.67 ; R9_3.2@4031.01,5447.67 R9_3.2@4027.08,5447.67
  Signal w10: v2(4030,5350) 4122.87,5442.87 5546.38,5442.87 6077.14,4912.12 6077.14,2082.14 6002.51,2007.51 5654.63,2007.51 v2(5617.62,1970.5)
  Bottom Layer w7.87: U4_3.3@5425.85,1894.08 5427.11,1895.33 v2(5428.77,1895.33) 5426.86,1897.24 5426.86,1904.12 5423.04,1907.93 5423.04,1942.22 5430.58,1949.76 5520.02,1949.76 5520.34,1949.44 5596.26,1949.44 5617.33,1970.5 v2(5617.62,1970.5)
BATSN4: J8_4.2 R9_4.2 R39_4.2 U4_4.3 U6_4.1 | length 4843.1
  Top Layer w7.87: J8_4.2@5388.84,5575.83 5466.05,5498.62 5466.05,5447.64 5472.86,5440.83 5480.73,5440.83 5472.86,5432.95 v2(5472.86,5345.68)
  Signal w10: v2(5348.33,1972.31) 5347.07,1973.57 5347.07,2000.52 5389.81,2043.26 5984.1,2043.26 6029.53,2088.69 6029.53,4561.99 5758.65,4832.86 5758.65,5153.97 5566.94,5345.68 v2(5472.86,5345.68)
  Bottom Layer w7.87: v2(5164.55,1895.64) 5160.53,1895.64 U4_4.3@5159.31,1894.42 5159.31,1897.05 5165.66,1897.05 5166.96,1898.36 5166.96,1948.04 5214.1,1995.18 5325.46,1995.18 v2(5348.33,1972.31)
BATSP1: J8_1.1 R6_1.2 R16_1.2 R32_1.2 U4_1.1 U6_1.4 | length 9767.3
  Top Layer w7.87: R6_1.2@865.26,5444.08 865.26,5494.82 J8_1.1@949.52,5579.08 ; v2(5996.75,1826.98) 6000.55,1830.79 R32_1.2@6000.55,1832.01 ; R32_1.2@5999.46,1826.98 5997.17,1829.28 5977.29,1829.28 5966.24,1840.32 5966.24,1892.7 6040.31,1966.76 v2(6095.89,1966.76) ; R32_1.2@6002.52,1830.04 R32_1.2@6010.05,1837.57 ; U6_1.4@6098.84,1963.2 6098.84,1963.81 v2(6095.89,1966.76) ; U6_1.4@6099.46,1954.39 6099.46,1963.2 v2(6095.89,1966.76)
  Signal w10: v2(865.55,5444.08) 894.63,5415 1139.16,5415 1220.66,5496.5 5659.78,5496.5 5874.59,5281.69 5874.65,5281.69 5888.05,5268.29 5888.05,5268.23 6155,5001.28 6155,2037.34 6098.19,1980.53 6098.19,1969.06 v2(6095.89,1966.76)
  Bottom Layer w7.87: v2(865.55,5444.08) 955,5354.63 955,5082.64 1154.89,4882.76 v2(1184.35,4882.76)
BATSP2: J8_2.1 R6_2.2 R16_2.2 R32_2.2 U4_2.1 U6_2.4 | length 8408.9
  Top Layer w7.87: R6_2.2@2285.37,5451.6 2285.37,5485.11 2352.08,5551.82 2352.08,5565.11 J8_2.1@2369.64,5582.67 ; v2(2539.86,4901.34) 2566.97,4901.34 2567.21,4901.1 2589.71,4901.1 R16_2.2@2604.47,4886.34 ; v2(5713.49,1834.33) 5713.49,1834.88 5713.79,1835.18 5716.17,1835.18 R32_2.2@5723.75,1842.75 ; R32_2.2@5713.49,1837.86 5712.43,1838.91 5695.46,1838.91 5690.85,1843.52 5690.85,1903.34 5744.88,1957.38 U6_2.4@5815.65,1957.38 ; v2(5815.65,1966.76) 5815.65,1961.09 5819.63,1957.11 5819.63,1954.04 U6_2.4@5819.89,1953.78
  Signal w10: v2(2278.89,5450) 2303.89,5425 2415,5425 ; v2(2539.86,4901.34) 2517.92,4901.34 2375,5044.26 2375,5385 2415,5425 ; v2(5815.65,1966.76) 5815.65,1968.33 5836.96,1989.64 6043.52,1989.64 6105,2051.12 6105,4955.09 5599.35,5460.75 2605.75,5460.75 2570,5425 2415,5425
BATSP3: J8_3.1 R6_3.2 R16_3.2 R32_3.2 U4_3.1 U6_3.4 | length 7155.7
  Top Layer w7.87: v2(3785,5315) 3785,5316.14 3760.37,5340.77 3760.37,5498.04 3814.03,5551.7 3849.46,5551.7 J8_3.1@3870.42,5572.67 ; v2(3968.85,4936.34) 4018.85,4886.34 R16_3.2@4079.47,4886.34 ; v2(5430.58,1837.33) 5434.42,1841.17 R32_3.2@5434.42,1848.89 5430.48,1848.89 5419.11,1860.27 5413.78,1860.27 5406.86,1867.19 5406.86,1925.14 5454.03,1972.31 5529.49,1972.31 5538.34,1963.46 U6_3.4@5538.34,1954.3 ; U6_3.4@5535.68,1963.46 v2(5535.68,1972.31)
  Signal w10: v2(3968.85,4936.34) 3903.7,4936.34 3891.64,4948.4 3891.64,5115.61 3785,5222.26 v2(3785,5315) 3797.13,5327.13 4039.47,5327.13 4137.35,5425 5535.09,5425 6059.26,4900.83 6059.26,2093.14 5991.5,2025.39 5621.41,2025.39 5568.33,1972.31 v2(5535.68,1972.31)
BATSP4: J8_4.1 R6_4.2 R16_4.2 R32_4.2 U4_4.1 U6_4.4 | length 5625.6
  Top Layer w7.87: R32_4.2@5172.62,1853.83 5168.68,1853.83 5157.45,1842.59 5157.45,1839.99 v2(5154.79,1837.33) 5126.96,1865.16 5126.96,1891.76 5137.5,1902.31 5137.5,1903.66 5194.45,1960.61 U6_4.4@5270.3,1960.61 5267.77,1963.14 v2(5267.77,1972.31) ; v2(5290.41,5331.28) 5288.72,5331.28 5202.22,5417.78 R6_4.2@5202.22,5440.83 5202.22,5487.63 J8_4.1@5290.41,5575.83 ; v2(5464.98,4894.5) 5466.28,4893.2 5511.55,4893.2 R16_4.2@5525.25,4879.5
  Signal w10: v2(5267.77,1972.31) 5270.3,1972.31 5359.12,2061.13 5972.05,2061.13 6009.44,2098.52 6009.44,4556.8 5738.24,4827.99 5738.24,5149.1 5572.35,5315 5309.96,5315 ; v2(5290.41,5331.28) 5309.96,5311.73 5309.96,5049.52 v2(5464.98,4894.5)
Board_temp: C93.1 J13.30 R122.1 | length 4764.2
  Top Layer w7.87: v2(3074.41,2783.07) C93.1@3130,2783.07 ; v2(5141.87,213.29) 5141.87,210.01 5145.14,206.75 5145.14,195.19 5151.04,189.28 J13.30@5151.04,175.5
  Signal w7.87: v2(3074.41,2783.07) 3048.36,2757.03 3048.36,950.99 3046.49,949.11 3046.49,930.16 3059.89,916.77 3062.54,916.77 3178.14,801.17 3375.58,801.17 3389.83,786.92 v2(3392.54,786.92)
  Bottom Layer w7.87: v2(3392.54,786.92) 3392.54,182.46 3429.49,145.51 5071.38,145.51 5139.17,213.29 v2(5141.87,213.29)
C2K_Vout1: C95.2 J13.31 R118.2 | length 244.3
  Top Layer w7.87: J13.31@5119.54,309.36 5124.39,314.2 5124.39,410.75 5129.79,416.15 5173.45,416.15 5192.69,435.4 5192.69,445.46 5194.2,446.96 5194.2,450.07 5202.07,457.94 C95.2@5202.07,461.88 R118.2@5234.07,461.88
C2K_Vout2: C96.2 J13.33 R119.2 | length 232.2
  Top Layer w7.87: J13.33@5088.05,309.36 5092.89,314.2 5092.89,406.41 5120.8,434.32 5145.45,434.32 5169.07,457.94 5165.14,461.88 C96.2@5135.07,461.88
C2K_Vout3: C97.2 J13.37 R120.2 | length 203.2
  Top Layer w7.87: J13.37@5025.06,309.36 5029.9,314.2 5029.9,407.98 5063.26,441.34 5063.26,455.07 C97.2@5070.07,461.88 R120.2@5102.07,461.88
C2K_Vout4: C98.2 J13.39 R121.2 | length 203
  Top Layer w7.87: J13.39@4993.56,309.36 4993.56,413.43 5038.07,457.94 C98.2@5038.07,461.88 R121.2@5006.07,461.88
CAN_GND: C105.1 J16.2 U22.9 U22.10 U22.15 | length 962.2
  Bottom Layer w7.87: U22.9@1843.51,739.27 U22.10@1893.51,739.27 1893.51,718.6 1932.03,680.07 2104.98,680.07 2143.51,718.6 U22.15@2143.51,739.27 2143.51,820.89 C105.1@2144.89,822.27
  Bottom Layer w10: C105.1@2144.89,822.27 2144.89,990.46 J16.2@2383.27,1228.85
CAN_VCC: C105.2 J16.1 U22.16 | length 652.8
  Bottom Layer w7.87: U22.16@2193.51,759.94 2208.34,774.76 2211.16,774.76 2481.7,1045.3 J16.1@2481.7,1228.85
  Bottom Layer w10: C105.2@2192.13,822.27 2193.29,821.11 2193.29,760.16 U22.16@2193.51,759.94
CANH: J15.1 R164.2 U22.13 | length 499.7
  Bottom Layer w7.87: J15.1@2042.72,1224.38 2042.72,864.23 R164.2@2060.68,846.27 2060.68,777.11 2043.51,759.94 U22.13@2043.51,739.27
CANL: J15.2 R164.1 U22.12 | length 576.7
  Bottom Layer w7.87: J15.2@1944.29,1224.38 1944.29,1074.29 1885,1014.99 1885,877.68 1910.63,852.06 1925.92,852.06 1942.54,835.44 R164.1@1946.51,835.44 ; R164.1@1946.51,846.27 R164.1@1946.51,835.44 ; U22.12@1993.51,739.27 1993.51,759.94 1950.79,802.65 1950.79,831.15 R164.1@1946.51,835.44
CANRX: R155.2 U22.3 | length 2533.6
  Signal w7.87: v2(2108,257.46) 2722.46,257.46 2746.84,281.84 4222.37,281.84 4239.32,264.89 v2(4240.77,264.89)
  Bottom Layer w7.87: U22.3@2093.51,355.41 2093.51,273.8 2108,259.31 v2(2108,257.46) ; v2(4155.93,507) 4158.88,507 4241.69,424.19 4241.69,265.8 v2(4240.77,264.89)
CANTX: R153.2 U22.6 | length 2497.7
  Signal w7.87: v2(2284.47,216.26) 2287.16,216.26 2312.52,190.9 2930.26,190.9 2994.74,255.38 3303.2,255.38 3355.55,203.02 3489.48,203.02 3542.02,255.56 v2(4016.77,255.56)
  Bottom Layer w7.87: U22.6@1943.51,355.41 1943.51,334.74 2062.6,215.64 2283.85,215.64 v2(2284.47,216.26) ; v2(4016.77,255.56) 4031.43,270.22 4031.43,314.33 4018.16,327.6 4018.16,480.94 4043.58,506.36 v2(4043.58,507)
CONVST: R76.2 R135.2 U16.68 | length 1014.4
  Top Layer w7.87: U16.68@5146.16,1008.38 5169.49,1008.38 5174.42,1013.3 5175.39,1013.3 5187.5,1025.41 5187.5,1027.97 5192.52,1032.98 R76.2@5218.2,1032.98
  Bottom Layer w7.87: v2(4870,509.13) 4906.45,545.58 5139.22,545.58 5247.24,653.61 5247.24,897.12 5293.63,943.5 5293.63,1039.35 5272.23,1060.75 5242.85,1060.75 v2(5222.39,1040.28)
CSn_DAC: R149.2 U17.12 | length 870.4
  Top Layer w7.87: U17.12@3865.53,659.76 3865.53,653.22 3865.81,652.95 3868.58,652.95 3897.9,623.64 3968.07,623.64 3973.98,629.55 4020.82,629.55 4069.05,581.33 4309.69,581.33 4309.92,581.55 4598.95,581.55 4648.19,532.32 4648.19,515.94 R149.2@4655,509.13
CSnA: R68.2 R70.1 R148.1 R154.1 TP10.1 U16.63 | length 2152.8
  Top Layer w7.87: v2(4331.08,510.1) 4331.08,507.73 R148.1@4333.3,505.5 ; U16.63@5146.16,880.42 5169.49,880.42 5174.42,875.5 5175.39,875.5 5191.73,859.16 5191.73,843.77 5212.19,823.31 5215.95,823.31 5225.43,813.83 v2(5225.43,810.06)
  Bottom Layer w7.87: v2(4331.08,510.1) 4328.73,510.1 4314.48,495.85 4272.55,495.85 4260.77,507.63 4260.77,508.74 4241.34,528.18 4216.11,528.18 v2(4194.93,507) 4255.93,446 4464.63,446 4502.4,483.77 4502.4,537.65 4526.07,561.33 5105.05,561.33 5225.43,681.71 TP10.1@5225.43,715.5 v2(5225.43,810.06) 5169.89,865.61 5078.35,865.61 5037.68,824.94 4892.58,824.94 4873.67,843.85 4751.41,843.85 v2(4731.81,824.25)
EN_RLY1: R26_1.2 R160.1 U2_1.5 | length 6898.4
  Top Layer w7.87: U2_1.5@1511.25,4960.87 1524.85,4960.87 1529.77,4955.94 1529.77,4942.25 1547.86,4924.16 1559.5,4912.52 1564.59,4912.52 v2(1579.35,4897.76)
  Signal w7.87: v2(1536.07,2405) 1536.07,1745.29 1533.19,1742.4 1533.19,830.73 1997.43,366.49 2838.18,366.49 2908.82,437.13 3865.34,437.13 3929.11,500.89 3929.11,507.35 v2(3931.43,509.67) ; v2(1579.35,4897.76) v2@1582.35,4894.76
  Bottom Layer w7.87: v2(1536.07,2405) 1473.19,2467.89 1473.19,4773.09 1559.66,4859.56 1559.66,4878.06 v2(1579.35,4897.76)
EN_RLY2: R26_2.2 R161.1 U2_2.5 | length 6051.3
  Top Layer w7.87: U2_2.5@2931.37,4964.45 2951.06,4964.45 2955.98,4959.53 2955.98,4956.68 2957.74,4954.91 2957.74,4937.98 2974.9,4920.83 2977.46,4920.83 2982.18,4916.1 2984.71,4916.1 v2(2999.47,4901.34)
  Signal w7.87: v2(2635,441) 2671,405 2854.42,405 2902.29,452.87 3848.45,452.87 3892.25,496.68 3892.25,496.94 3893.78,498.47 3893.78,505.6 v2(3896.1,507.92) ; v2(2725,1550) 2725,1833.38 2945,2053.38 v2(2945,2320)
  Bottom Layer w7.87: v2(2635,441) 2622.46,453.54 2622.46,1447.46 v2(2725,1550) ; v2(2945,2320) 2943.98,2321.02 2943.98,4845.85 v2(2999.47,4901.34)
EN_RLY3: R26_3.2 R162.1 U2_3.5 | length 7438.2
  Top Layer w7.87: U2_3.5@4406.37,4964.45 4426.06,4964.45 4442.98,4947.53 4442.98,4920.75 4448.69,4915.04 4460.77,4915.04 R26_3.2@4474.47,4901.34
  Signal w7.87: v2(2675,470) 3840.85,470 3857.45,486.61 v2(3857.45,509.13) ; v2(4437.85,1608.66) 4460,1630.81 v2(4460,2310)
  Bottom Layer w7.87: v2(2675,470) 2660.94,484.06 2660.94,1410.5 2813.62,1563.19 4008.42,1563.19 4058.78,1613.56 4429.68,1613.56 4434.57,1608.66 v2(4437.85,1608.66) ; v2(4460,2310) 4460,4881.7 4475.23,4896.93 v2(4475.23,4900.18)
EN_RLY4: R26_4.2 R163.1 U2_4.5 | length 8331.4
  Top Layer w7.87: U2_4.5@5852.15,4957.61 5866.29,4957.61 5870.15,4953.75 5870.15,4934.85 5895.74,4909.26 5905.49,4909.26 v2(5920.25,4894.5)
  Signal w7.87: v2(2710,500) 3807.24,500 3814.59,507.34 v2(3817.87,507.34) ; v2(4635.96,1591.71) 5129.62,2085.37 v2(5715.79,2085.37)
  Bottom Layer w7.87: v2(2710,500) 2710,1099.98 2708.87,1101.11 2708.87,1134.87 2710,1136 2710,1434.29 2823.15,1547.44 4017.95,1547.44 4052.61,1582.1 4329.82,1582.1 4342.66,1569.25 4613.51,1569.25 v2(4635.96,1591.71) ; v2(5715.79,2085.37) 5920.25,2289.84 v2(5920.25,4894.5)
EXTSYNCOUT: J3.1 R140.2 | length 2019.8
  Top Layer w7.87: R140.2@4525,509.13 v2(4525,510.1)
  Signal w7.87: v2(4525,510.1) 4568.09,553.19 5008.28,553.19 5018.81,563.72 5713.72,563.72 6258.49,1108.49 6286.58,1108.49 J3.1@6293.25,1115.16
Gate_1: Q2_1.4 Q3_1.4 R18_1.1 R21_1.1 | length 610.7
  Top Layer w10: R21_1.1@1067.8,5192.76 R18_1.1@1142.98,5192.76
  Signal w7.87: v2(586.06,5148.46) 589.34,5148.46 595.82,5141.99 683.69,5141.99 743.16,5201.46 v2(744.9,5201.46) 783.44,5240 1023.77,5240 v2(1062.32,5201.46)
Gate_2: Q2_2.4 Q3_2.4 R18_2.1 R21_2.1 | length 628.2
  Top Layer w10: v2(2337.64,5157.43) 2448.03,5157.43 2486.93,5196.34 R18_2.1@2563.09,5196.34
  Signal w7.87: v2(2006.18,5152.05) 2037.81,5183.68 2143.04,5183.68 2158.33,5198.98 v2(2158.58,5198.98) 2210.9,5146.66 2230,5146.66 2241.63,5135.03 2254.83,5135.03 2277.23,5157.43 v2(2337.64,5157.43)
Gate_3: Q2_3.4 Q3_3.4 R18_3.1 R21_3.1 | length 639.6
  Top Layer w20: v2(3812.64,5157.43) 3934.09,5157.43 3953.23,5176.58 3953.23,5187.64 R21_3.1@3961.93,5196.34 ; R21_3.1@3962.92,5196.34 R21_3.1@3961.93,5196.34 ; R18_3.1@4038.09,5196.34 R21_3.1@3961.93,5196.34
  Signal w7.87: v2(3481.18,5152.05) 3537.34,5152.05 3551.2,5138.19 3591.5,5138.19 3633.58,5180.28 v2(3633.58,5198.98) 3674.93,5198.98 3683.91,5190 3780.07,5190 v2(3812.64,5157.43)
Gate_4: Q2_4.4 Q3_4.4 R18_4.1 R21_4.1 | length 648.7
  Top Layer w20: v2(5258.42,5150.59) 5387.29,5150.59 5399.01,5162.31 5399.01,5180.8 R21_4.1@5407.71,5189.5 ; R21_4.1@5408.7,5189.5 R21_4.1@5407.71,5189.5 ; R18_4.1@5483.87,5189.5 R21_4.1@5407.71,5189.5
  Signal w7.87: v2(4926.96,5145.21) 5032.43,5145.21 v2(5079.36,5192.14) 5112.22,5225 5184.01,5225 v2(5258.42,5150.59)
HO_1: R8_1.1 U3_1.4 | length 113.5
  Top Layer w7.87: U3_1.4@818.54,2839.92 v2(838.72,2839.92)
  Bottom Layer w7.87: v2(838.72,2839.92) 886.6,2887.8 v2(912.24,2887.8)
HO_2: R8_2.1 U3_2.4 | length 113.5
  Top Layer w7.87: U3_2.4@2238.66,2843.5 2239.26,2844.1 2259.98,2844.1 v2(2260.58,2844.69)
  Bottom Layer w7.87: v2(2260.58,2844.69) 2307.26,2891.38 v2(2332.36,2891.38)
HO_3: R8_3.1 U3_3.4 | length 113.5
  Top Layer w7.87: U3_3.4@3713.66,2843.5 v2(3733.84,2843.5)
  Bottom Layer w7.87: v2(3733.84,2843.5) 3781.72,2891.38 v2(3807.36,2891.38)
HO_4: R8_4.1 U3_4.4 | length 113.5
  Top Layer w7.87: U3_4.4@5159.44,2836.67 v2(5179.62,2836.67)
  Bottom Layer w7.87: v2(5179.62,2836.67) 5227.5,2884.54 v2(5253.14,2884.54)
HW_RNGSEL0: R82.2 U16.39 | length 273.1
  Top Layer w7.87: R82.2@4424.15,661.05 4437.85,674.76 4458.62,674.76 4494.59,710.72 4494.59,849.05 4500.37,854.83 U16.39@4535.93,854.83
HW_RNGSEL1: R83.2 U16.38 | length 235.7
  Top Layer w7.87: R83.2@4428.35,708.14 4478.84,758.62 4478.84,855.58 4498.76,875.5 4507.67,875.5 4512.59,880.42 U16.38@4535.93,880.42
ILN1: C7_1.1 C8_1.1 C10_1.1 C11_1.1 C15_1.1 C16_1.1 C17_1.1 C108_1.2 L1_1.2 R1_1.1 R4_1.2 R165.1 | length 5613.5
  Top Layer w7.87: C15_1.1@1155.09,3881.42 1155.09,3874.92 1315.69,3714.32 1444.32,3714.32 v2(1445,3715) ; v2(5045.3,1676.57) 5045.53,1676.34 5045.3,1642.7 R165.1@5045.53,1642.46
  Bottom Layer w7.87: v2(1445,3715) 1457.44,3702.56 1457.44,2442.86 1984.32,1915.98 4862.95,1915.98 5045.3,1733.64 v2(5045.3,1676.57)
  other v1: 693.85,3719.73 723.53,3719.73 752.67,3719.73 782.67,3719.73 812.67,3719.73 843.63,3719.73 873.32,3719.73 902.45,3719.73 932.45,3719.73 962.45,3719.73 997.47,3719.73 1027.15,3719.73 1056.29,3719.73 1086.29,3719.73 1116.29,3719.73 711.6,3766.44 741.29,3766.44 770.42,3766.44 800.42,3766.44 830.42,3766.44 863.51,3766.44 893.19,3766.44 922.33,3766.44 952.33,3766.44 982.33,3766.44 1016.6,3766.44 1046.29,3766.44 1075.42,3766.44 1105.42,3766.44 1135.42,3766.44 1139.58,3855.35 1137.25,3895.48 1090.21,3902.76 1090.21,3932.45 1140.17,3954.3 1090.21,3961.58 1140.17,3984.3 1090.21,3991.58 1140.17,4014.3 1090.21,4021.58 1156.41,4032.06 1090.21,4054.67 1131.35,4074.95 1090.21,4084.35 1131.35,4104.09 1090.21,4113.49 1131.35,4134.09 1090.21,4143.49 1057.4,4368.29 1087.4,4368.29 1116.54,4368.29 1146.22,4368.29 1040.69,4412.45 1077.28,4415 1107.28,4415 1136.41,4415 550.65,4462.78 580.34,4462.78 609.47,4462.78 639.47,4462.78 669.47,4462.78 700.44,4462.78 730.12,4462.78 759.26,4462.78 789.26,4462.78 568.41,4509.49 598.09,4509.49 627.23,4509.49 657.23,4509.49 687.23,4509.49 720.32,4509.49 750,4509.49 779.14,4509.49 809.14,4509.49
ILN2: C7_2.1 C8_2.1 C10_2.1 C11_2.1 C15_2.1 C16_2.1 C17_2.1 C108_2.2 L1_2.2 R1_2.1 R4_2.2 R169.1 | length 4376.7
  Top Layer w7.87: C15_2.1@2587.17,3881.44 C15_2.1@2587.17,3887.94 ; C108_2.2@2622.39,3687.67 2626.33,3687.67 2642.08,3703.41 2642.08,3704.37 2652.71,3715 v2(2760,3715) ; R169.1@4975.53,1642.46 4975.53,1709.9 5013.8,1748.17 5013.8,1812.93 5030.57,1829.69 5030.57,1845.71 v2(5031.63,1846.78)
  Bottom Layer w7.87: v2(2760,3715) 2840.85,3715 2892.48,3663.37 2892.48,2045.56 2953.05,1985 4890.27,1985 5028.5,1846.78 v2(5031.63,1846.78)
  other v1: 2122.54,3734.73 2152.22,3734.73 2181.36,3734.73 2211.36,3734.73 2241.36,3734.73 2272.32,3734.73 2302.01,3734.73 2331.14,3734.73 2361.14,3734.73 2391.14,3734.73 2426.16,3734.73 2455.84,3734.73 2484.98,3734.73 2514.98,3734.73 2544.98,3734.73 2140.29,3781.44 2169.98,3781.44 2199.11,3781.44 2229.11,3781.44 2259.11,3781.44 2292.2,3781.44 2321.88,3781.44 2351.02,3781.44 2381.02,3781.44 2411.02,3781.44 2445.29,3781.44 2474.98,3781.44 2504.11,3781.44 2534.11,3781.44 2564.11,3781.44 2564.42,3903.43 2517.71,3921.18 2576.12,3930 2517.71,3950.87 2564.42,3962.24 2517.71,3980 2564.42,3992.24 2517.71,4010 2564.42,4022.24 2517.71,4040 2564.42,4053.21 2517.71,4073.09 2564.42,4082.9 2517.71,4102.77 2564.42,4112.03 2517.71,4131.91 2564.42,4142.03 2517.71,4161.91 2480.72,4370 2510.72,4370 2539.86,4370 2569.54,4370 2464.01,4414.16 2500.6,4416.71 2530.6,4416.71 2559.73,4416.71 1973.97,4464.49 2003.66,4464.49 2032.79,4464.49 2062.79,4464.49 2092.79,4464.49 2123.76,4464.49 2153.44,4464.49 2182.58,4464.49 2212.58,4464.49 1991.73,4511.2 2021.41,4511.2 2050.55,4511.2 2080.55,4511.2 2110.55,4511.2 2143.64,4511.2 2173.32,4511.2 2202.46,4511.2 2232.46,4511.2
ILN3: C7_3.1 C8_3.1 C10_3.1 C11_3.1 C15_3.1 C16_3.1 C17_3.1 C108_3.2 L1_3.2 R1_3.1 R4_3.2 R173.1 | length 2825.6
  Top Layer w7.87: C108_3.2@4097.39,3687.67 4101.33,3687.67 4117.08,3703.41 4117.08,3704.37 4124,3711.29 4165.28,3711.29 4240,3636.56 v2(4240,3635) ; R173.1@4907.37,1642.46 4907.37,1823.37 5001.45,1917.45 5028.96,1917.45 v2(5029.32,1917.09)
  Bottom Layer w7.87: v2(4240,3635) 4365,3510 4365,2163.42 4473.11,2055.31 4905.56,2055.31 5024.81,1936.05 5024.81,1924.88 5029.32,1920.37 v2(5029.32,1917.09)
  other v1: 3599.71,3739.73 3629.4,3739.73 3658.53,3739.73 3688.53,3739.73 3718.53,3739.73 3749.5,3739.73 3779.18,3739.73 3808.32,3739.73 3838.32,3739.73 3868.32,3739.73 3903.34,3739.73 3933.02,3739.73 3962.15,3739.73 3992.15,3739.73 4022.15,3739.73 3617.47,3786.44 3647.15,3786.44 3676.29,3786.44 3706.29,3786.44 3736.29,3786.44 3769.38,3786.44 3799.06,3786.44 3828.19,3786.44 3858.19,3786.44 3888.19,3786.44 3922.47,3786.44 3952.15,3786.44 3981.29,3786.44 4011.29,3786.44 4041.29,3786.44 4041.39,3908.43 3994.89,3926.18 4041.6,3938.11 3994.89,3955.87 4041.6,3967.24 3994.89,3985 4041.6,3997.24 3994.89,4015 4041.6,4027.24 3994.89,4045 3994.89,4078.09 4042.69,4083.86 3994.89,4107.77 4042.69,4113 3994.89,4136.91 4042.69,4143 3994.89,4166.91 4042.69,4171.81 3957.9,4375 3987.9,4375 4017.03,4375 4046.72,4375 3941.19,4419.16 3977.78,4421.71 4007.78,4421.71 4036.91,4421.71 3481.15,4456.99 3510.84,4456.99 3539.97,4456.99 3569.97,4456.99 3599.97,4456.99 3630.94,4456.99 3660.62,4456.99 3689.75,4456.99 3719.75,4456.99 3498.91,4503.7 3528.59,4503.7 3557.73,4503.7 3587.73,4503.7 3617.73,4503.7 3650.81,4503.7 3680.5,4503.7 3709.63,4503.7 3739.63,4503.7
ILN4: C7_4.1 C8_4.1 C10_4.1 C11_4.1 C15_4.1 C16_4.1 C17_4.1 C108_4.2 L1_4.2 R1_4.1 R4_4.2 R177.1 | length 2841.4
  Top Layer w7.87: R177.1@4837.02,1642.46 4837.02,1810.45 4996.57,1970 v2(5073.42,1970) ; C108_4.2@5543.17,3680.83 5547.11,3680.83 5562.86,3696.57 5562.86,3697.53 5569.77,3704.45 5611.06,3704.45 5725,3590.5 v2(5725,3590)
  Top Layer w10: R1_4.1@5038.23,4464.63 R1_4.1@5038.23,4479.41
  Bottom Layer w7.87: v2(5073.42,1970) 5253.62,2150.21 5640.14,2150.21 5725,2235.06 v2(5725,3590)
  other v1: 5059.64,3726.5 5089.32,3726.5 5118.46,3726.5 5148.46,3726.5 5178.46,3726.5 5209.42,3726.5 5239.11,3726.5 5268.24,3726.5 5298.24,3726.5 5328.24,3726.5 5363.26,3726.5 5392.94,3726.5 5422.08,3726.5 5452.08,3726.5 5482.08,3726.5 5077.39,3773.21 5107.08,3773.21 5136.21,3773.21 5166.21,3773.21 5196.21,3773.21 5229.3,3773.21 5258.99,3773.21 5288.12,3773.21 5318.12,3773.21 5348.12,3773.21 5382.39,3773.21 5412.08,3773.21 5441.21,3773.21 5471.21,3773.21 5501.21,3773.21 5500.53,3858.68 5500.53,3893.87 5454.81,3912.95 5454.81,3942.63 5505,3970 5454.81,3971.77 5454.81,4001.77 5505,4009.93 5454.81,4031.77 5505,4033.15 5454.81,4064.86 5502.06,4071.5 5454.81,4094.54 5502.06,4100.64 5454.81,4123.68 5502.06,4130.64 5454.81,4153.68 5417.82,4361.77 5447.82,4361.77 5476.96,4361.77 5401.11,4405.93 5437.7,4408.48 5467.7,4408.48 5496.84,4408.48 4921.05,4464.63 4950.74,4464.63 4979.87,4464.63 5009.87,4464.63 5039.87,4464.63 5070.84,4464.63 5100.52,4464.63 5129.66,4464.63 4938.81,4511.34 4968.49,4511.34 4997.63,4511.34 5027.63,4511.34 5057.63,4511.34 5090.72,4511.34 5120.4,4511.34
ILP1: C108_1.1 R42_1.1 R43.1 | length 5303.6
  Top Layer w7.87: R42_1.1@1271.01,3529.08 1272,3529.08 1487.34,3313.74 1492.68,3313.74 v2(1495,3311.42) ; R43.1@5080.95,1642.46 5081.65,1643.17 5081.65,1675.87 v2(5082.36,1676.57)
  Top Layer w20: C108_1.1@1249.52,3684.08 1253.45,3684.08 1255.27,3682.27 1255.27,3678.33 1271.01,3662.59 R42_1.1@1271.01,3529.08
  Bottom Layer w7.87: v2(1495,3311.42) 1557.89,3248.53 1557.89,2396.27 2014.9,1939.25 4861.95,1939.25 5082.36,1718.85 v2(5082.36,1676.57)
ILP2: C108_2.1 R42_2.1 R167.1 | length 4234.3
  Top Layer w7.87: R42_2.1@2691.13,3532.67 2703.8,3520 v2(2790,3520) ; R167.1@5011.6,1642.46 5011.6,1721.49 5035.61,1745.5 v2(5035.61,1803.89)
  Top Layer w20: C108_2.1@2669.64,3687.67 2673.57,3687.67 2675.38,3685.85 2675.38,3681.92 2691.13,3666.17 R42_2.1@2691.13,3532.67
  Bottom Layer w7.87: v2(2790,3520) 2876.31,3433.69 2876.31,2013.99 2935.31,1955 4892.14,1955 4962.72,1884.42 4962.72,1876.79 v2(5035.61,1803.89)
ILP3: C108_3.1 R42_3.1 R171.1 | length 2749.6
  Top Layer w7.87: R171.1@4942.37,1642.46 4942.37,1827.53 v2(5010.48,1895.64)
  Top Layer w10: C108_3.1@4144.64,3687.67 4148.57,3687.67 4155.38,3680.85 4155.38,3676.92 4235,3597.3 v2(4235,3550) 4232.29,3550 4216.42,3534.13 4208.44,3534.13 4206.98,3532.67 R42_3.1@4166.13,3532.67
  Bottom Layer w7.87: v2(4235,3550) 4235,2887.6 4347.5,2775.1 4347.5,2158.65 4470.09,2036.05 4878.45,2036.05 4943.3,1971.2 4943.3,1962.82 v2(5010.48,1895.64)
ILP4: C108_4.1 R42_4.1 R175.1 | length 2815.4
  Top Layer w7.87: R175.1@4871.56,1642.46 4871.56,1822.72 4989.76,1940.92 5057.7,1940.92 v2(5060,1943.22) ; v2(5611.91,3525.83) 5626.68,3511.06 5741.48,3511.06 5751.72,3500.83 v2(5755,3500.83)
  Top Layer w20: C108_4.1@5590.42,3680.83 5594.35,3680.83 5596.16,3679.02 5596.16,3675.08 5611.91,3659.33 v2(5611.91,3525.83)
  Bottom Layer w7.87: v2(5060,1943.22) 5078.18,1943.22 5269.42,2134.46 5646.66,2134.46 5755,2242.79 v2(5755,3500.83)
IOCP1: C35_1.1 R51_1.1 R124.2 U7_1.1 | length 1979.6
  Top Layer w7.87: C35_1.1@3858.78,988.26 v2(3816.32,988.26) 3816.32,992.2 3837.72,1013.6 3840.81,1013.6 3865.43,1038.22 U7_1.1@3865.43,1051.96 ; R124.2@5408.07,509.13 5409.62,509.13 v2(5410.49,508.25)
  Signal w7.87: v2(3816.32,988.26) 3818.21,988.26 3832.69,973.78 3838.26,973.78 3949.15,862.89 4005.82,862.89 4142.75,725.96 4633.28,725.96 4656.03,703.2 4827.91,703.2 4872.78,748.07 5201.12,748.07 5270.3,678.9 v2(5270.3,678.04)
  Power w7.87: v2(5270.3,678.04) 5271.15,678.04 5410.49,538.7 v2(5410.49,508.25)
IOCP2: C35_2.1 R51_2.1 R127.2 U7_2.1 | length 3367.9
  Top Layer w7.87: v2(3533.43,987.82) 3534.28,988.67 3576.39,988.67 C35_2.1@3577.24,987.82 ; R51_2.1@3533.43,991.54 3541.3,999.41 3550.49,999.41 3550.49,1008.79 3573.35,1031.64 3585.51,1031.64 3589.08,1035.2 U7_2.1@3589.08,1047.37 ; v2(5336.99,504.66) 5338.61,504.66 R127.2@5343.07,509.13
  Bottom Layer w7.87: v2(3533.43,987.82) 3533.43,984.54 3522.46,973.57 3522.46,967.45 3334.05,779.03 3334.05,201.9 3336.47,199.47 3336.47,189.56 3416.27,109.76 5143.76,109.76 5147.62,113.62 5150.62,113.62 5166.35,129.35 5209.32,129.35 5270.3,190.32 5270.3,437.97 v2(5336.99,504.66)
IOCP3: C35_3.1 R51_3.1 R126.2 U7_3.1 | length 3474.5
  Top Layer w7.87: v2(3187.13,950.32) 3225.89,989.08 3244.78,989.08 R51_3.1@3248.72,993.02 ; R51_3.1@3248.72,993.02 R51_3.1@3257.59,993 ; C35_3.1@3290.29,993.02 3292.22,991.08 3292.49,991.08 3259.51,991.08 R51_3.1@3257.59,993 ; U7_3.1@3295.37,1062.29 3295.37,1045.91 3295.61,1045.67 3264.4,1014.46 3264.4,999.81 R51_3.1@3257.59,993 ; R126.2@5376.07,509.13 v2(5376.88,509.13)
  Bottom Layer w7.87: v2(3187.13,950.32) 3189.45,948 3189.45,931.12 3196,924.57 3196,251.35 3355.46,91.89 5148.15,91.89 5154.14,97.87 5203.35,97.87 5305,199.53 5305,423.63 5376.01,494.64 5376.01,508.25 v2(5376.88,509.13)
